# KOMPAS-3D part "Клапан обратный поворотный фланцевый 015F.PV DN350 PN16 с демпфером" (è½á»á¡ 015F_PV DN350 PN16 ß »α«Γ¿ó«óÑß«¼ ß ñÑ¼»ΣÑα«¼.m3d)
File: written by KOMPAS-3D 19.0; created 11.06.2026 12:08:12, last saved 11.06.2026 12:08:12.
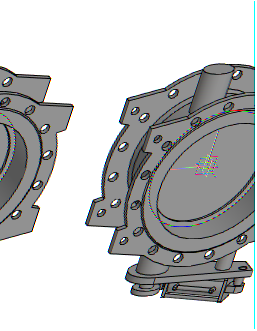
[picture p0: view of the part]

Document properties: Автор: Энергия; Полное имя файла: Z:\3.Личные\kachalov\001_3d для проектировщиков\5.5 Тип 015F.PV Клапан обратный поворотный с двумя эксцентриками\_stp_Клапан 015F.PV DN300-DN1200 с противовесом с демпфером\Клапан 015F_PV DN350 PN16 с противовесом с демпфером.m3d

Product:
- Part/product: Клапан обратный поворотный фланцевый 015F.PV DN350 PN16 с демпфером

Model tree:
1. Операция без истории:1
2. Сплайн:1
     Координата Y = 30; Координата Z = 175; Вес = 1; Координата X = 350; Координата Y = 76.0784; Координата Z = 175; Вес = 0.333333; Координата X = 350; Координата Y = 76.0784; Координата Z = -175; Вес = 0.333333; Координата Y = 30; Координата Z = -175; Вес = 1; Координата X = -350; Координата Y = -16.0784; Координата Z = -175; Вес = 0.333333; Координата X = -350; Координата Y = -16.0784; Координата Z = 175; Вес = 0.333333; Порядок = 4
